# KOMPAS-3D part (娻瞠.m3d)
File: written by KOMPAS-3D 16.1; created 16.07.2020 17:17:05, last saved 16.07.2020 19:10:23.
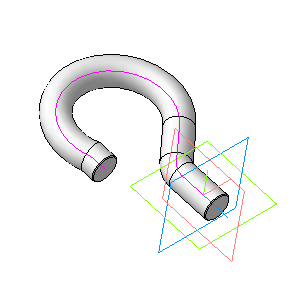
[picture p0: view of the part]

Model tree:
1. Эскиз:1
2. Эскиз:2
3. Кинематическая операция:1
4. Операция выдавливания:1
     Расстояние 1 = 10
5. Фаска:1
     Угол = 45; Длина 1 = 0.5; Длина 2 = 0.5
